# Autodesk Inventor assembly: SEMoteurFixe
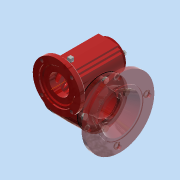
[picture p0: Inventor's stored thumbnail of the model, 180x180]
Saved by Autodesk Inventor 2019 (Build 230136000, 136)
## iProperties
Created: 2023-02
Part Number: SEMoteurFixe
Material: Générique
Document SubType Name: Assembly
Designer: Thier
Author: Thier
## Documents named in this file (11)
- C:\Travail\PREPA\EC02\TP\TP3-Arbre\EC02-T03-Pieces-SEMoteur\SERecepteurFixe.iam
- C:\Travail\PREPA\EC02\TP\TP3-Arbre\EC02-T03-Pieces-SEMoteur\23-Corps.ipt
- C:\Travail\PREPA\EC02\TP\TP3-Arbre\EC02-T03-Pieces-SEMoteur\25-Couvercle.ipt
- C:\Users\Thier\OneDrive\Documents\Inventor\Content Center Files\R2019\fr-FR\ISO 4017(1)\ISO 4017 - M5 x 12 - ISO.ipt
- C:\Travail\PREPA\EC02\TP\TP3-Arbre\EC02-T03-Pieces-SEMoteur\28-Joint Plat.ipt
- C:\Users\Thier\OneDrive\Documents\Inventor\Content Center Files\R2019\fr-FR\ISO 4145 T8\ISO 4145 Bouchon mâle T8 1_8.ipt
- C:\Users\Thier\OneDrive\Documents\Inventor\Content Center Files\R2019\fr-FR\DIN 906 ISK\DIN 906 - M8x1 keg - ISK.ipt
- C:\Travail\PREPA\EC02\TP\TP3-Arbre\EC02-T03-Pieces-SEMoteur\26-Flasque.ipt
- C:\Travail\PREPA\EC02\TP\TP3-Arbre\EC02-T03-Pieces-SEMoteur\32-FlasqueOuvert.ipt
- C:\Travail\PREPA\EC02\TP\TP3-Arbre\EC02-T03-Pieces-SEMoteur\NF E 25-516 - WZ7.ipt
- C:\Users\Thier\OneDrive\Documents\Inventor\Content Center Files\R2019\fr-FR\ISO 4017(1)\ISO 4017 - M6 x 20 - ISO.ipt
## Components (24 placed, 10 different names)
1. 23-Corps:1 — Logement:1, Logement:2, Angle:1, Angle:2, Angle:3, Logement:6, Logement:7, Placage:1, Logement:8, Placage:2, Placage:3, Logement:9, Placage:4, Placage:6
2. 25-Couvercle:1 — Logement:1, Logement:2, Angle:8, Angle:9, Angle:12, Angle:13
3. ISO 4017 M5 x 12:1 — Angle:1
4. ISO 4017 M5 x 12:2 — Angle:3
5. ISO 4017 M5 x 12:3 — Angle:2
6. 28-Joint Plat:1 — Placage:1, Logement:8, Angle:4, Logement:10, Logement:11
7. 28-Joint Plat:2 — Logement:6, Logement:7, Angle:5, Logement:16
8. ISO 4145 Bouchon mâle T8 1/8:1 — Placage:2, Angle:4, Placage:3
9. ISO 4145 Bouchon mâle T8 1/8:2 — Logement:9, Angle:5
10. DIN 906 ISK M8x1 keg:1 — Placage:4
11. 26-Flasque:1 — Logement:10, Logement:11, Logement:12, Logement:13, Logement:14, Logement:15
12. ISO 4017 M6 x 20:1 — Angle:6, Logement:14
13. ISO 4017 M6 x 20:2 — Angle:6, Angle:8, Logement:12
14. ISO 4017 M6 x 20:3 — Angle:7, Angle:9, Logement:13
15. ISO 4017 M6 x 20:4 — Angle:7, Logement:15
16. ISO 4017 M6 x 20:5 — Angle:10, Angle:12
17. ISO 4017 M6 x 20:6 — Angle:10, Placage:5
18. ISO 4017 M6 x 20:7 — Angle:11
19. ISO 4017 M6 x 20:8 — Angle:11, Angle:13
20. 32-FlasqueOuvert:1 — Logement:16, Placage:5, Placage:6
21. NF E 25-516 WZ7:1
22. NF E 25-516 WZ7:2
23. NF E 25-516 WZ7:3
24. NF E 25-516 WZ7:4
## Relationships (32: Insert 13, Angle 13, Mate 6)
- Logement:1 [Insert]: 23-Corps:1 ↔ 25-Couvercle:1
- Logement:2 [Insert]: 23-Corps:1 ↔ 25-Couvercle:1
- Angle:1: 23-Corps:1 ↔ ISO 4017 M5 x 12:1
- Angle:2: 23-Corps:1 ↔ ISO 4017 M5 x 12:3
- Angle:3: 23-Corps:1 ↔ ISO 4017 M5 x 12:2
- Logement:6 [Insert]: 23-Corps:1 ↔ 28-Joint Plat:2
- Logement:7 [Insert]: 23-Corps:1 ↔ 28-Joint Plat:2
- Placage:1 [Mate]: 23-Corps:1 ↔ 28-Joint Plat:1
- Logement:8 [Insert]: 23-Corps:1 ↔ 28-Joint Plat:1
- Placage:2 [Mate]: 23-Corps:1 ↔ ISO 4145 Bouchon mâle T8 1/8:1
- Angle:4: 28-Joint Plat:1 ↔ ISO 4145 Bouchon mâle T8 1/8:1
- Placage:3 [Mate]: 23-Corps:1 ↔ ISO 4145 Bouchon mâle T8 1/8:1
- Logement:9 [Insert]: 23-Corps:1 ↔ ISO 4145 Bouchon mâle T8 1/8:2
- Angle:5: 28-Joint Plat:2 ↔ ISO 4145 Bouchon mâle T8 1/8:2
- Placage:4 [Mate]: 23-Corps:1 ↔ DIN 906 ISK M8x1 keg:1
- Angle:6: ISO 4017 M6 x 20:1 ↔ ISO 4017 M6 x 20:2
- Angle:7: ISO 4017 M6 x 20:3 ↔ ISO 4017 M6 x 20:4
- Angle:8: 25-Couvercle:1 ↔ ISO 4017 M6 x 20:2
- Angle:9: 25-Couvercle:1 ↔ ISO 4017 M6 x 20:3
- Angle:10: ISO 4017 M6 x 20:5 ↔ ISO 4017 M6 x 20:6
- Angle:11: ISO 4017 M6 x 20:7 ↔ ISO 4017 M6 x 20:8
- Angle:12: 25-Couvercle:1 ↔ ISO 4017 M6 x 20:5
- Angle:13: 25-Couvercle:1 ↔ ISO 4017 M6 x 20:8
- Logement:10 [Insert]: 28-Joint Plat:1 ↔ 26-Flasque:1
- Logement:11 [Insert]: 28-Joint Plat:1 ↔ 26-Flasque:1
- Logement:12 [Insert]: 26-Flasque:1 ↔ ISO 4017 M6 x 20:2
- Logement:13 [Insert]: 26-Flasque:1 ↔ ISO 4017 M6 x 20:3
- Logement:14 [Insert]: 26-Flasque:1 ↔ ISO 4017 M6 x 20:1
- Logement:15 [Insert]: 26-Flasque:1 ↔ ISO 4017 M6 x 20:4
- Logement:16 [Insert]: 28-Joint Plat:2 ↔ 32-FlasqueOuvert:1
- Placage:5 [Mate]: ISO 4017 M6 x 20:6 ↔ 32-FlasqueOuvert:1
- Placage:6 [Mate]: 23-Corps:1 ↔ 32-FlasqueOuvert:1
